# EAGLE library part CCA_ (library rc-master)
CHIP CAP ARRAY
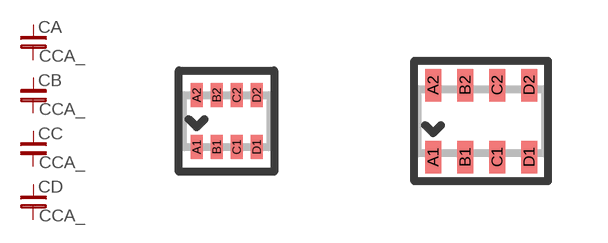
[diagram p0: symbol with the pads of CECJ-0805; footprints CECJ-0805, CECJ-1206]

Designator prefix C; gates A=CNP- B=CNP- C=CNP- D=CNP-

## CCA_ECJ-0805  [CECJ-0805]
A1  A:1  pas
A2  A:2  pas
B1  B:1  pas
B2  B:2  pas
C1  C:1  pas
C2  C:2  pas
D1  D:1  pas
D2  D:2  pas

## CCA_ECJ-1206  [CECJ-1206]
Pads as for CECJ-0805

## Footprint CECJ-0805 (pad centres in mm)
CAPACITOR ARRAY - Panasonic 0.8 mm lead spacing, ECJ-0805 Series, grid 0.05 mm
smd 0.305 x 0.61: A1 -0.75,-0.65; A2 -0.75,0.65; B1 -0.25,-0.65; B2 -0.25,0.65; C1 0.25,-0.65; C2 0.25,0.65; D1 0.75,-0.65; D2 0.75,0.65

## Footprint CECJ-1206 (pad centres in mm)
CAPACITOR ARRAY - Panasonic 0.8 mm lead spacing, ECJ-1206 Series, grid 0.10 mm
smd 0.406 x 0.813: A1 -1.2,-0.9; A2 -1.2,0.9; B1 -0.4,-0.9; B2 -0.4,0.9; C1 0.4,-0.9; C2 0.4,0.9; D1 1.2,-0.9; D2 1.2,0.9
